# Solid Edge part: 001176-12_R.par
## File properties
Last saved by: morva
Revision: 82
Accuracy: 0.990
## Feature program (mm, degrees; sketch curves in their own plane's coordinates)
body "unnamed Body 1"
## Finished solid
Body 1: solid body, 27 faces, 61 edges, 36 vertices.
  Faces by surface: cone 11, plane 8, torus 4, cylinder 2, sphere 2
  Edges by curve: circle 29, curve on surface 19, line 13
Bounding box of the edges (mm; curved faces can reach further): 12.969 x 9.822 x 12.888, from (376.9841, 378.238, 148.9033) to (389.9531, 388.0599, 161.791).
Cylindrical faces by radius (mm): R2.25 x2
Conical faces (half-angle, radius in mm at the cone's reference point): 45 deg R3.25 x4, 45 deg R5.7781 x7
Toroidal faces (ring radius, tube radius in mm): R3.5195 r3.0222 x4
Spherical faces by radius (mm): R11.5625 x2
Planar faces by outward normal: oblique 8
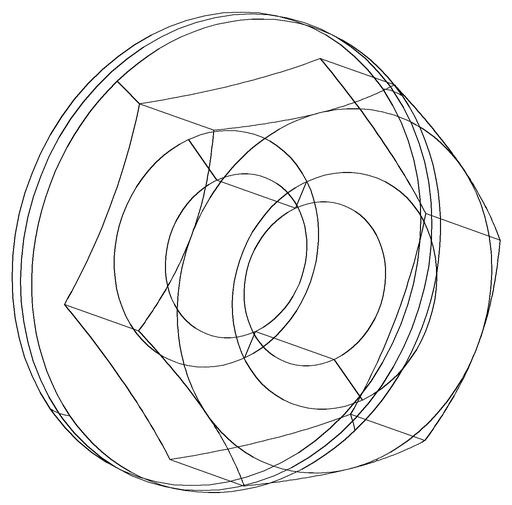
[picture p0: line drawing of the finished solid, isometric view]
